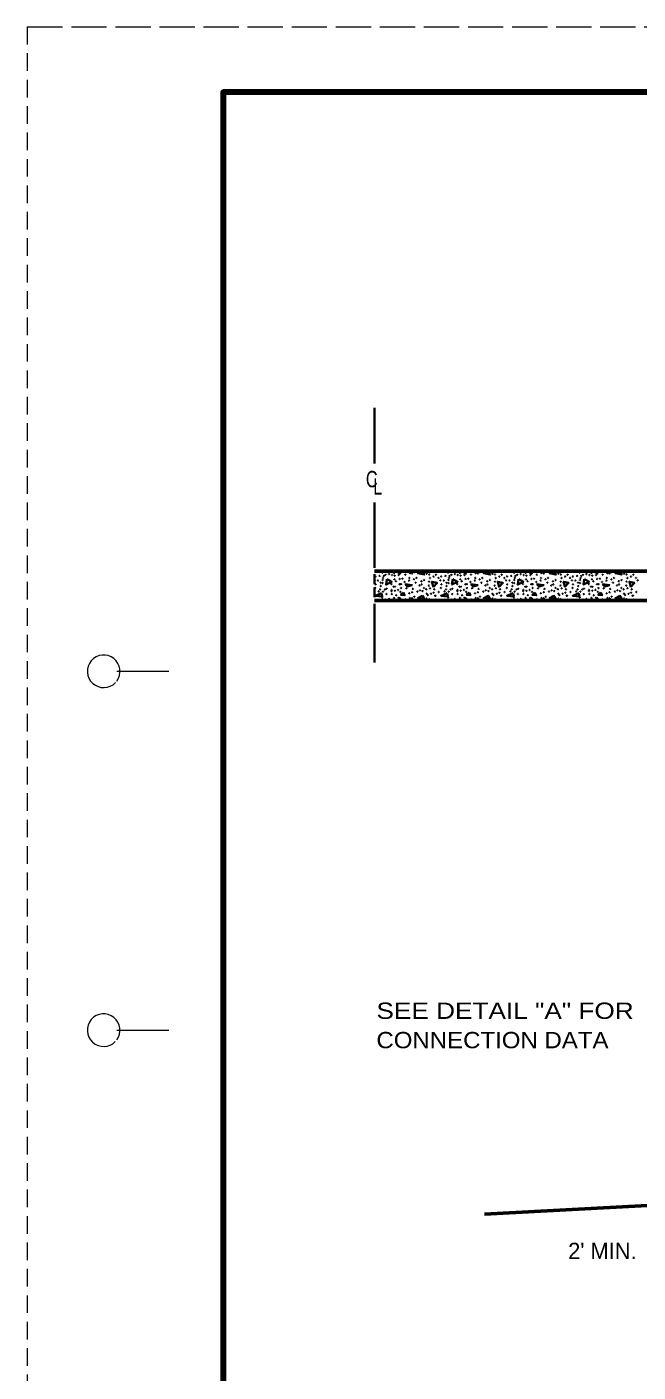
# Model space of a CAD drawing. Extents: x -54 to 626, y -41 to 399.
# Drawn here: x -54.4 to 39.2, y 192.5 to 398.7 of the extents above; entities that cross this region are included whole.
import ezdxf

# ---------------------------------------------------------------- set-up
doc = ezdxf.new("R2010")
doc.units = 0
doc.header["$LTSCALE"] = 0.9
doc.linetypes.add('LONG_DASHED', pattern=[7.5, 6, -1.5])
doc.linetypes.add('MEDIUM_DASHED', pattern=[4.5, 3, -1.5])
doc.layers.add('1', color=7, linetype='Continuous', lineweight=35)
doc.layers.add('61', color=7, linetype='Continuous', lineweight=35)

msp = doc.modelspace()

# ---------------------------------------------------------------- linework, layer by layer
at = {"layer": '1', "linetype": 'MEDIUM_DASHED', "lineweight": 13}
msp.add_line((-54.3422, 398.7039), (-54.4022, -41.3361), dxfattribs=at)
at = {"layer": '1'}
for p, q in [((-1.1842, 331.8082), (-1.1842, 340.3082)), ((-1.1842, 315.8082), (-1.1842, 325.8082)), ((-1.1842, 314.8082), (-1.1842, 313.3082)), ((-1.1842, 312.8082), (-1.1842, 311.3082)), ((-1.1842, 310.3082), (-1.1842, 301.3082))]:
    msp.add_line(p, q, dxfattribs=at)
at = {"layer": '1', "lineweight": 53}
for p, q in [((79.3158, 310.8082), (-1.1842, 310.8082)), ((54.6281, 218.8097), (15.6813, 216.7685))]:
    msp.add_line(p, q, dxfattribs=at)
msp.add_lwpolyline([(-1.1842, 315.3082), (79.3158, 315.3082), (79.3158, 313.3054), (79.3158, 310.8082)], dxfattribs=at)
at = {"layer": '1'}
for points in [[(-0.9528, 315.3082), (-0.0082, 315.1993), (-0.0318, 315.3082)], [(0.7718, 314.0592), (1.4718, 313.6592), (0.6118, 313.2392), (0.7318, 314.0793)], [(7.8718, 312.8592), (7.6318, 313.6592), (8.4118, 313.4993), (7.8518, 312.8992)], [(9.1272, 315.3082), (10.0718, 315.1993), (10.0482, 315.3082)], [(10.8518, 314.0592), (11.5518, 313.6592), (10.6918, 313.2392), (10.8118, 314.0793)], [(17.9518, 312.8592), (17.7118, 313.6592), (18.4918, 313.4993), (17.9318, 312.8992)], [(19.2072, 315.3082), (20.1518, 315.1993), (20.1282, 315.3082)], [(20.9318, 314.0592), (21.6318, 313.6592), (20.7718, 313.2392), (20.8918, 314.0793)], [(26.2917, 315.3082), (25.6518, 314.9592), (26.6318, 314.7792), (26.2918, 315.3082)], [(28.0318, 312.8592), (27.7918, 313.6592), (28.5718, 313.4993), (28.0118, 312.8992)], [(29.2872, 315.3082), (30.2318, 315.1993), (30.2082, 315.3082)], [(31.0118, 314.0592), (31.7118, 313.6592), (30.8518, 313.2392), (30.9718, 314.0793)], [(38.1118, 312.8592), (37.8718, 313.6592), (38.6518, 313.4993), (38.0918, 312.8992)], [(-0.1082, 311.8992), (-1.0482, 311.5192), (-0.0082, 311.3992), (-0.1082, 311.8592)], [(3.2518, 312.0392), (2.8718, 311.6393), (3.4518, 311.5992), (3.2518, 311.9993)], [(6.1518, 311.5192), (5.4918, 311.1592), (6.4718, 310.9792), (6.1118, 311.5392)], [(9.9718, 311.8992), (9.0318, 311.5192), (10.0718, 311.3992), (9.9718, 311.8592)], [(13.3318, 312.0392), (12.9518, 311.6393), (13.5318, 311.5992), (13.3318, 311.9993)], [(16.2318, 311.5192), (15.5718, 311.1592), (16.5518, 310.9792), (16.1918, 311.5392)], [(20.0518, 311.8992), (19.1118, 311.5192), (20.1518, 311.3992), (20.0518, 311.8592)], [(23.4118, 312.0392), (23.0318, 311.6393), (23.6118, 311.5992), (23.4118, 311.9993)], [(26.3118, 311.5192), (25.6518, 311.1592), (26.6318, 310.9792), (26.2718, 311.5392)], [(30.1318, 311.8992), (29.1918, 311.5192), (30.2318, 311.3992), (30.1318, 311.8592)], [(33.4918, 312.0392), (33.1118, 311.6393), (33.6918, 311.5992), (33.4918, 311.9993)], [(36.3918, 311.5192), (35.7318, 311.1592), (36.7118, 310.9792), (36.3518, 311.5392)]]:
    msp.add_lwpolyline(points, dxfattribs=at)
for points in [[(6.1317, 315.3082), (5.4918, 314.9592), (6.4718, 314.7792)], [(16.2117, 315.3082), (15.5718, 314.9592), (16.5518, 314.7792)], [(36.3717, 315.3082), (35.7318, 314.9592), (36.7118, 314.7792)], [(3.5318, 313.2792), (4.5718, 313.1592), (3.8918, 312.9192)], [(13.6118, 313.2792), (14.6518, 313.1592), (13.9718, 312.9192)], [(23.6918, 313.2792), (24.7318, 313.1592), (24.0518, 312.9192)], [(33.7718, 313.2792), (34.8118, 313.1592), (34.1318, 312.9192)]]:
    msp.add_lwpolyline(points, close=True, dxfattribs=at)
for centre in [(-1.027, 314.4779), (-0.6427, 313.8548), (-0.3776, 314.5708), (-0.2186, 313.5234), (0.02, 315.0612), (0.073, 313.4571), (0.0862, 313.9344), (0.1525, 314.2393), (0.2585, 314.5575), (0.5368, 314.7298), (1.0669, 314.8491), (1.5176, 314.7033), (1.8356, 314.995), (1.8886, 314.0405), (1.9417, 314.5972), (2.114, 313.7487), (2.5248, 315.0082), (2.538, 314.69), (2.6971, 314.0935), (2.7578, 314.9287), (3.1155, 314.1465), (3.4469, 313.6295), (3.5396, 314.7563), (4.1229, 313.8548), (4.1758, 314.2526), (4.2553, 314.9817), (4.6, 314.942), (4.865, 314.0405), (4.918, 315.1806), (5.1433, 313.5234), (5.2626, 314.2526), (6.018, 313.7487), (6.4288, 313.9211), (6.8265, 314.8889), (7.1975, 313.6825), (7.2108, 314.7961), (7.3301, 314.226), (7.8735, 314.4647), (8.2446, 314.743), (8.6421, 314.2526), (8.9204, 313.8814), (9.053, 314.4779), (9.4373, 313.8548), (9.7024, 314.5708), (9.8614, 313.5234), (10.1, 315.0612), (10.153, 313.4571), (10.1662, 313.9344), (10.2325, 314.2393), (10.3385, 314.5575), (10.6168, 314.7298), (11.1469, 314.8491), (11.5976, 314.7033), (11.9156, 314.995), (11.9686, 314.0405), (12.0217, 314.5972), (12.194, 313.7487), (12.6048, 315.0082), (12.618, 314.69), (12.7771, 314.0935), (12.8378, 314.9287), (13.1955, 314.1465), (13.5269, 313.6295), (13.6196, 314.7563), (14.2029, 313.8548), (14.2558, 314.2526), (14.3353, 314.9817), (14.68, 314.942), (14.945, 314.0405), (14.998, 315.1806), (15.2233, 313.5234), (15.3426, 314.2526), (16.098, 313.7487), (16.5088, 313.9211), (16.9065, 314.8889), (17.2775, 313.6825), (17.2908, 314.7961), (17.4101, 314.226), (17.9535, 314.4647), (18.3246, 314.743), (18.7221, 314.2526), (19.0004, 313.8814), (19.133, 314.4779), (19.5173, 313.8548), (19.7824, 314.5708), (19.9414, 313.5234), (20.18, 315.0612), (20.233, 313.4571), (20.2462, 313.9344), (20.3125, 314.2393), (20.4185, 314.5575), (20.6968, 314.7298), (21.2269, 314.8491), (21.6776, 314.7033), (21.9956, 314.995), (22.0486, 314.0405), (22.1017, 314.5972), (22.274, 313.7487), (22.6848, 315.0082), (22.698, 314.69), (22.8571, 314.0935), (22.9178, 314.9287), (23.2755, 314.1465), (23.6069, 313.6295), (23.6996, 314.7563), (24.2829, 313.8548), (24.3358, 314.2526), (24.4153, 314.9817), (24.76, 314.942), (25.025, 314.0405), (25.078, 315.1806), (25.3033, 313.5234), (25.4226, 314.2526), (26.178, 313.7487), (26.5888, 313.9211), (26.9865, 314.8889), (27.3575, 313.6825), (27.3708, 314.7961), (27.4901, 314.226), (28.0335, 314.4647), (28.4046, 314.743), (28.8021, 314.2526), (29.0804, 313.8814), (29.213, 314.4779), (29.5973, 313.8548), (29.8624, 314.5708), (30.0214, 313.5234), (30.26, 315.0612), (30.313, 313.4571), (30.3262, 313.9344), (30.3925, 314.2393), (30.4985, 314.5575), (30.7768, 314.7298), (31.3069, 314.8491), (31.7576, 314.7033), (32.0756, 314.995), (32.1286, 314.0405), (32.1817, 314.5972), (32.354, 313.7487), (32.7648, 315.0082), (32.778, 314.69), (32.9371, 314.0935), (32.9978, 314.9287), (33.3555, 314.1465), (33.6869, 313.6295), (33.7796, 314.7563), (34.3629, 313.8548), (34.4158, 314.2526), (34.4953, 314.9817), (34.84, 314.942), (35.105, 314.0405), (35.158, 315.1806), (35.3833, 313.5234), (35.5026, 314.2526), (36.258, 313.7487), (36.6688, 313.9211), (37.0665, 314.8889), (37.4375, 313.6825), (37.4508, 314.7961), (37.5701, 314.226), (38.1135, 314.4647), (38.4846, 314.743), (38.8821, 314.2526), (39.1604, 313.8814), (-1.0668, 312.728), (-1.0006, 313.2715), (-0.5102, 312.1893), (-0.2981, 312.5026), (-0.2053, 313.0063), (0.126, 312.1495), (0.4043, 312.4761), (0.6561, 311.7783), (0.6826, 312.5953), (1.4248, 313.3113), (1.4513, 312.2423), (1.4646, 312.4098), (1.491, 311.7915), (1.7562, 312.9135), (1.9549, 312.2953), (1.9814, 312.9135), (2.167, 311.606), (2.4453, 312.4231), (2.6774, 313.2825), (2.8108, 312.1097), (2.9035, 313.2981), (2.9035, 312.7014), (3.712, 312.6617), (4.1493, 311.8976), (4.6, 312.0699), (4.706, 312.5821), (4.918, 311.3806), (5.4084, 312.1627), (5.7397, 313.1124), (5.806, 312.3568), (6.0578, 313.2583), (6.2035, 312.229), (6.4024, 312.7147), (6.7602, 312.5158), (6.8264, 311.8313), (6.9855, 311.6192), (7.1578, 313.0859), (7.3433, 312.6617), (7.5023, 311.8313), (7.9, 311.9904), (7.9927, 312.5158), (8.1253, 311.5264), (8.1783, 311.5264), (8.6819, 312.0964), (9.0132, 312.728), (9.0794, 313.2715), (9.5698, 312.1893), (9.7819, 312.5026), (9.8747, 313.0063), (10.206, 312.1495), (10.4843, 312.4761), (10.7361, 311.7783), (10.7626, 312.5953), (11.5048, 313.3113), (11.5313, 312.2423), (11.5446, 312.4098), (11.571, 311.7915), (11.8362, 312.9135), (12.0349, 312.2953), (12.0614, 312.9135), (12.247, 311.606), (12.5253, 312.4231), (12.7574, 313.2825), (12.8908, 312.1097), (12.9835, 313.2981), (12.9835, 312.7014), (13.792, 312.6617), (14.2293, 311.8976), (14.68, 312.0699), (14.786, 312.5821), (14.998, 311.3806), (15.4884, 312.1627), (15.8197, 313.1124), (15.886, 312.3568), (16.1378, 313.2583), (16.2835, 312.229), (16.4824, 312.7147), (16.8402, 312.5158), (16.9064, 311.8313), (17.0655, 311.6192), (17.2378, 313.0859), (17.4233, 312.6617), (17.5823, 311.8313), (17.98, 311.9904), (18.0727, 312.5158), (18.2053, 311.5264), (18.2583, 311.5264), (18.7619, 312.0964), (19.0932, 312.728), (19.1594, 313.2715), (19.6498, 312.1893), (19.8619, 312.5026), (19.9547, 313.0063), (20.286, 312.1495), (20.5643, 312.4761), (20.8161, 311.7783), (20.8426, 312.5953), (21.5848, 313.3113), (21.6113, 312.2423), (21.6246, 312.4098), (21.651, 311.7915), (21.9162, 312.9135), (22.1149, 312.2953), (22.1414, 312.9135), (22.327, 311.606), (22.6053, 312.4231), (22.8374, 313.2825), (22.9708, 312.1097), (23.0635, 313.2981), (23.0635, 312.7014), (23.872, 312.6617), (24.3093, 311.8976), (24.76, 312.0699), (24.866, 312.5821), (25.078, 311.3806), (25.5684, 312.1627), (25.8997, 313.1124), (25.966, 312.3568), (26.2178, 313.2583), (26.3635, 312.229), (26.5624, 312.7147), (26.9202, 312.5158), (26.9864, 311.8313), (27.1455, 311.6192), (27.3178, 313.0859), (27.5033, 312.6617), (27.6623, 311.8313), (28.06, 311.9904), (28.1527, 312.5158), (28.2853, 311.5264), (28.3383, 311.5264), (28.8419, 312.0964), (29.1732, 312.728), (29.2394, 313.2715), (29.7298, 312.1893), (29.9419, 312.5026), (30.0347, 313.0063), (30.366, 312.1495), (30.6443, 312.4761), (30.8961, 311.7783), (30.9226, 312.5953), (31.6648, 313.3113), (31.6913, 312.2423), (31.7046, 312.4098), (31.731, 311.7915), (31.9962, 312.9135), (32.1949, 312.2953), (32.2214, 312.9135), (32.407, 311.606), (32.6853, 312.4231), (32.9174, 313.2825), (33.0508, 312.1097), (33.1435, 313.2981), (33.1435, 312.7014), (33.952, 312.6617), (34.3893, 311.8976), (34.84, 312.0699), (34.946, 312.5821), (35.158, 311.3806), (35.6484, 312.1627), (35.9797, 313.1124), (36.046, 312.3568), (36.2978, 313.2583), (36.4435, 312.229), (36.6424, 312.7147), (37.0002, 312.5158), (37.0664, 311.8313), (37.2255, 311.6192), (37.3978, 313.0859), (37.5833, 312.6617), (37.7423, 311.8313), (38.14, 311.9904), (38.2327, 312.5158), (38.3653, 311.5264), (38.4183, 311.5264), (38.9219, 312.0964), (0.02, 311.2612), (0.5368, 310.9298), (1.0669, 311.0491), (1.5176, 310.9033), (1.8356, 311.195), (2.5248, 311.2082), (2.538, 310.89), (2.7578, 311.1287), (3.5396, 310.9563), (4.2553, 311.1817), (4.6, 311.142), (6.8265, 311.0889), (7.2108, 310.9961), (8.2446, 310.943), (10.1, 311.2612), (10.6168, 310.9298), (11.1469, 311.0491), (11.5976, 310.9033), (11.9156, 311.195), (12.6048, 311.2082), (12.618, 310.89), (12.8378, 311.1287), (13.6196, 310.9563), (14.3353, 311.1817), (14.68, 311.142), (16.9065, 311.0889), (17.2908, 310.9961), (18.3246, 310.943), (20.18, 311.2612), (20.6968, 310.9298), (21.2269, 311.0491), (21.6776, 310.9033), (21.9956, 311.195), (22.6848, 311.2082), (22.698, 310.89), (22.9178, 311.1287), (23.6996, 310.9563), (24.4153, 311.1817), (24.76, 311.142), (26.9865, 311.0889), (27.3708, 310.9961), (28.4046, 310.943), (30.26, 311.2612), (30.7768, 310.9298), (31.3069, 311.0491), (31.7576, 310.9033), (32.0756, 311.195), (32.7648, 311.2082), (32.778, 310.89), (32.9978, 311.1287), (33.7796, 310.9563), (34.4953, 311.1817), (34.84, 311.142), (37.0665, 311.0889), (37.4508, 310.9961), (38.4846, 310.943)]:
    msp.add_circle(centre, 0.0265, dxfattribs=at)
for centre, start, end in [((-1.1596, 313.8814), 201.63508, 158.36492), ((8.1253, 315.3264), 223.38683, 316.61317), ((8.1783, 315.3264), 223.38683, 316.61317), ((18.2053, 315.3264), 223.38683, 316.61317), ((18.2583, 315.3264), 223.38683, 316.61317), ((28.2853, 315.3264), 223.38683, 316.61317), ((28.3383, 315.3264), 223.38683, 316.61317), ((38.3653, 315.3264), 223.38683, 316.61317), ((38.4183, 315.3264), 223.38683, 316.61317), ((1.9417, 310.7972), 24.63166, 155.36834), ((12.0217, 310.7972), 24.63166, 155.36834), ((22.1017, 310.7972), 24.63166, 155.36834), ((32.1817, 310.7972), 24.63166, 155.36834)]:
    msp.add_arc(centre, 0.0265, start, end, dxfattribs=at)
at = {"layer": '61', "linetype": 'LONG_DASHED', "lineweight": 13}
msp.add_line((-54.3422, 398.7039), (625.6777, 398.7039), dxfattribs=at)
at = {"layer": '61', "lineweight": 13}
for p, q in [((-40.6223, 299.9439), (-32.6422, 299.9639)), ((-40.6422, 244.9439), (-32.6422, 244.9439))]:
    msp.add_line(p, q, dxfattribs=at)
at = {"layer": '61', "lineweight": 158}
msp.add_lwpolyline([(614.6977, 388.7039), (-24.3422, 388.7039), (-24.3422, -31.3161)], dxfattribs=at)
at = {"layer": '61', "lineweight": 13}
for centre, end in [((-42.6445, 299.9452), 316.23216), ((-42.6445, 244.9452), 315.37577)]:
    msp.add_arc(centre, 2.5, 323.13009, end, dxfattribs=at)

# ---------------------------------------------------------------- texts
at = {"layer": '1'}
for s, width, p in [('C', 0.75, (-2.4865, 328.1506)), ('L', 0.75, (-1.3557, 327.0193)), ('SEE DETAIL "A" FOR', 1.2, (-0.8714, 246.6751)), ('CONNECTION DATA', 1.1, (-0.8714, 242.1751))]:
    msp.add_text(s, height=2.5, dxfattribs=dict(at, width=width)).set_placement(p)
msp.add_text("2' MIN.", height=2.5, dxfattribs=at).set_placement((28.496, 209.8607))

doc.saveas('drawing.dxf')
